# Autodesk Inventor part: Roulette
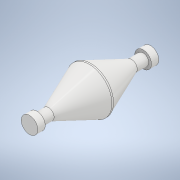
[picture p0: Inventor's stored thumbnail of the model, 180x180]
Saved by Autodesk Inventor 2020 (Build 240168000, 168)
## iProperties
Part Number: Roulette
Material: Générique
Document SubType Name: Modeling
Designer: Buhl
Density: 1 g/cm^3
Appearance: Par défaut
Mass: 1.21722 g
Surface Area: 7.24105 cm^2
Volume: 1.21722 cm^3
Author: Buhl
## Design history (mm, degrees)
sketch "Esquisse1"
  geometry: L1 (0, 0)-(41.177, 0); L2 (41.177, 0)-(9.177, 0); L3 (41.177, 0)-(41.177, -2.191); L4 (41.177, -2.191)-(39.223, -2.191); L5 (39.223, -2.191)-(39.223, -1.5); L6 (39.223, -1.5)-(36.177, -1.5); L7 (25.177, -6)-(25.177, 0); L8 (25.177, -6)-(25.386, -6); L9 (25.386, -6)-(36.177, -1.5)
  constraints: 18 end point, 3 perpendicular, 2 horizontal, 1 midpoint, 1 point on line, 1 vertical
  dimensions: "d0" = 32 distance of L1.end L2.end; "d1" = 6 distance from line of L1 L7.start; "d2" = 11 horizontal distance of L7.start L6.end; "d3" = 1.5 distance between parallel lines of L1 L6
revolve "Révolution1" sketch "Esquisse1" stored, may be unused: angle "d4" = 90 deg
mirror "Symétrie1"
node "Solide1"
